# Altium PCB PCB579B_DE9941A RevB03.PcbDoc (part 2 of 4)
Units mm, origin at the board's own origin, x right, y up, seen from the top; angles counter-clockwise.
Board outline 85.8 x 54.18 mm, 6 copper layers (Top, L2C, L3C, L4C, L5C, Bottom), stack 1.627 mm thick; 536 components, 371 nets, 1413 pads, 798 vias.
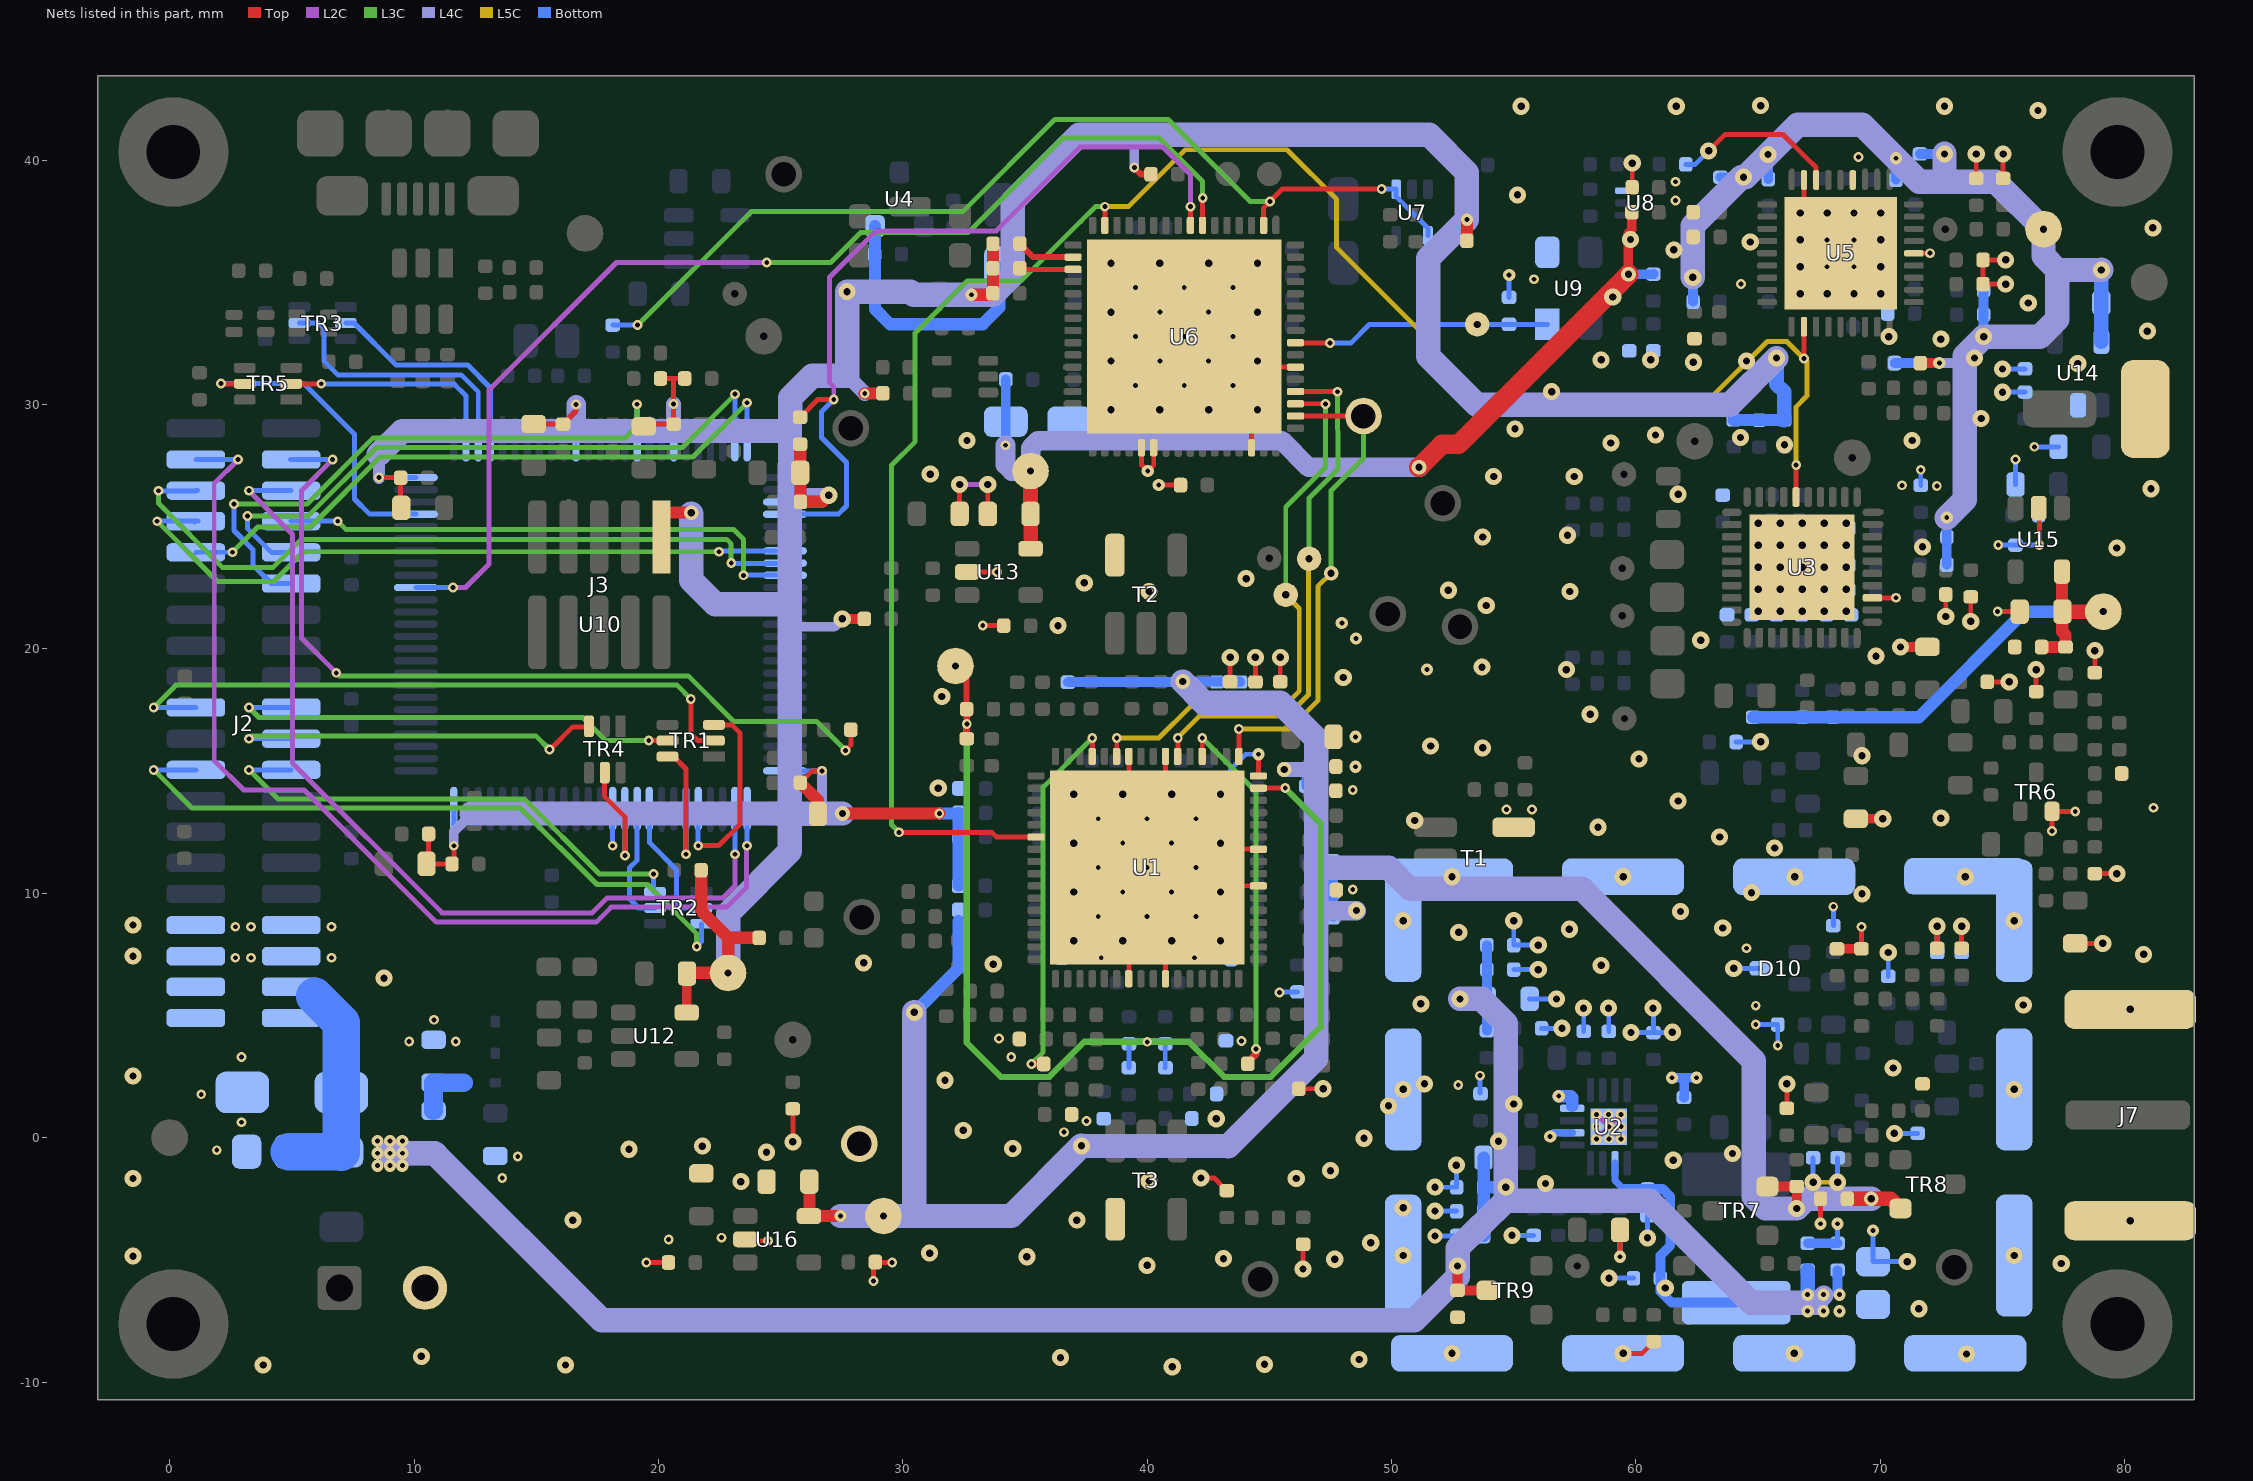
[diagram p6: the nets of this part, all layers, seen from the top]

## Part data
C1 C9 C10: library part CAP_TAJA_10uF_16V, "10uF 16V 10% TAJA Tant Capacitor"
C2 C3 C5 C6 C7 C8 C12 C15 C32 C35 C38 C41 C42 C44 C46 C47 C67 C68 C73 C75 C76 C80 C115 C117 C132 C139 C141 C143 C144 C146 C148 C153 C154 C156 C162 C165 C185: library part CAP0402_10000_X7R_25V_±10%, "0402 Cer. Cap. 10nF 25V X7R ±10%"
C4 C11 C20 C21 C22 C23 C24 C25 C34 C103 C104 C105 C106 C107 C108 C109 C111 C113 C114 C149 C150 C193: library part CAP0402_100000_X7R_16V_±10%, "0402 Cer. Cap. 100nF 16V X7R ±10%"
C13 C51 C52 C62 C69: library part "CAP0402_100p_C0G_25V_± 5%", "0402 Cer. Cap. 100pF±5% 25V C0G"
C14 C16 C17 C36 C50 C54 C59 C61 C70 C102 C110 C118 C126 C134 C135 C151 C152 C160 C163 C170 C186: library part "CAP0402_1000_C0G_25V_± 5%", "0402 Cer. Cap. 1000pF±5% 25V C0G"
C18 C45 C84 C87 C93 C96 C99 C116 C119 C122 C136 C138 C180 C183 C188 C189 C199: library part CAP0402_DNF, "Pads for 0402 Ceramic Capacitor"
C19 C33 C112: library part CAP0402_2200000_X5R_16V_±10%, "0402 Cer. Cap. 2.2uF 16V X5R ±10%"
C26 C27 C28 C29 C30 C31 C78 C81 C82 C86 C88 C89 C92 C94 C97 C194: library part CAP0603_10000000_X5R_10V_±20%, "0603 Cer. Cap. 10uF±20% 10V X5R"
C37 C39 C40 C43 C65 C66 C72 C74 C79 C131 C140 C142 C145 C147 C181: library part CAP0402_33p±5%_C0G_25V, "0402 Cer. Cap. 33pF±5% 25V C0G"
C48 C53 C71: library part "CAP0402_470p_C0G_25V_± 5%", "0402 Cer. Cap. 470pF±5% 25V C0G"
C49: library part CAP0402_47000_X7R_25V_±10%, "0402 Cer. Cap. 47nF 25V X7R ±10%"
C55 C57 C58 C60 C63 C64: library part CAP0402_33000_X7R_25V_±10%, "0402 Cer. Cap. 33nF 25V X7R ±10%"
C56: library part "CAP0402_220p_C0G_25V_± 5%", "0402 Cer. Cap. 220pF±5% 25V C0G"
C77: library part CAP0402_1000000_X5R_10V_±10%, "0402 Cer. Cap. 1uF 10V X5R ±10%"
C83 C85 C91 C95 C98 C155 C184 C196 C197: library part CAP0603_1000000_X7R_16V_±10%, "0603 Cer. Cap. 1uF±10% 16V X7R"
C90: library part CAP0805_DNF, "Unused pads for 0805 Ceramic Capacitor"
C100: library part CAP0402_4700_X7R_25V_±5%, "0402 Cer. Cap. 4.7nF 25V X7R ±5%"
C101: library part "CAP0402_180p_C0G_25V_± 5%", "0402 Cer. Cap. 180pF±5% 25V C0G"
C120 C121: library part CAP0402_10p±5%_C0G_25V, "0402 Cer. Cap. 10pF±5% 25V C0G"
C123 C125 C158 C159 C176 C178 C179 C182 C200: library part CAP0402_5p6±0.1pF_C0G_50V, "0402 Cer. Cap. 5.6pF±0.1pF 50V C0G"
C124: library part CAP0402_3p3±0.1pF_C0G_50V, "0402 Cer. Cap. 3.3pF±0.1pF 50V C0G"
C127 C128: library part CAP0603_2000_C0G_50V_±2%_0805, "0603 Cer. Cap. 2000pF±2% 50V C0G (on 0805 pads)"
C129 C130: library part "CAP0603_1500_C0G_50V_± 5%", "0603 Cer. Cap. 1500pF±5% 50V C0G"
C133 C172: library part CAP0402_1p5±0.1pF_C0G_50V, "0402 Cer. Cap. 1.5pF±0.1pF 50V C0G"
C137 C177 C190 C191: library part CAP0402_6p8±0.1pF_C0G_25V, "0402 Cer. Cap. 6.8pF±0.1pF 25V C0G"
C157 C173 C174 C175: library part "CAP0402_56p_C0G_25V_± 5%", "0402 Cer. Cap. 56pF±5% 25V C0G"
C161: library part CAP0805_10000000_X7R_10V_±10%, "0805 Cer. Cap. 10uF±10% 10V X7R"
C164: library part "CAP0402_330p_C0G_25V_± 5%", "0402 Cer. Cap. 330pF±5% 25V C0G"
C166 C167: library part CAP0402_0p5±0p05_C0G_50V, "0402 Cer. Cap. 0.5pF±0.05pF 50V C0G"
C168 C169: library part CAP0402_47p±5%_C0G_25V, "0402 Cer. Cap. 47pF±5% 25V C0G"
C171: library part CAP0402_2p0±0.1pF_C0G_25V, "0402 Cer. Cap. 2.0pF±0.1pF 25V C0G"
C187: library part CAP0402_4p7±0.1pF_C0G_50V, "0402 Cer. Cap. 4.7pF±0.1pF 50V C0G"
C192 R2 R3 R20 R24 R25 R35 R36 R80 R82 R107 R108 R109 R110 R119 R144 R145: library part R0402_0R, "Resistor 0402 0R 0.063W"
C195 C198: library part CAP0402_8p2±0.1pF_C0G_25V, "0402 Cer. Cap. 8.2pF±0.1pF 25V C0G"
D1: "BAS16HT,  Signal Diode, SOD323"
D2 D3: "HSMF-C165,  Mini Bi-colour Red+Green LED (0603)"
D4: library part LED0603_Green, "Green 0603 LED, KPT-1608CGCK"
D5 D6: "NSR05T40XV2,  Schottky Diode, SOD-523"
D7: library part SMAJ5_0A, "5V Transient Suppression Diode, DO-214AC"
D8: "MMBD1503A, Dual small signal diodes, SOT23"
D9 D10: "BAR64-04W,  Dual Si PIN diode SOT323"
F1: "MF-NSMF150, PTC Resettable Fuse, 1206"
FID1 FID2 FID3: "1.5mm round pad Fiducial"
J2: library part HDR_SMT_20x2_127, "20+20 SMT header, 1.27mm pitch (Archer M50 )"
J3: library part HDR_5X2_127_SMTUnshr, "5x2 header plug  1.27mm, SMT Unshrouded"
J4: library part USB-MICRO-B_ZX62, "R/A USB Micro-B receptacle (Hirose ZX62-B-5PA(33))"
J5: library part MKDS_2w_3_5mm, "2-WAY PCB screw terminal block - MKDS 1/ 2-3,5 HT BK"
J6: library part "RG178 PAD", "Pads for screened wire, e.g. RG 178"
J7: library part SMA_ENDL_J502, "J502 End Launch SMA Socket for 1.6mm PCBs"
L1: library part "Ferrite 0402 10R_BLM15AG100SN1", "0402 ferrite, Z=10R @ 100MHz, BLM15AG100SN1"
L2 L3: library part "Ferrite 0603_600R", "Ferrite, 0603, 600R @ 100MHz 1.3A"
L4 L6 L17 L18 L22: library part IND0603CS_18nH_5%, "Coilcraft 0603CS-18NXJL    Blue"
L5 L8: library part IND0603CS_DNF, "Pads for Coilcraft 0603 Inductor"
L7: library part IND0603CS_68nH_5%, "Coilcraft 0603CS-68NXJL   Orange"
L9 L10 L11: library part IND0603CS_27nH_5%, "Coilcraft 0603CS-27NXJL    Gray"
L12 L13: library part IND0603CS_100nH_5%, "Coilcraft 0603CS-R10XJL 100nH Blue"
L14: library part IND0402CS_5n6_5%, "0402 inductor, 5.6nH, 0402CS-5N6XJL"
L15: library part IND0603, "Coilcraft 0603CS"
L16: library part IND_1515SQ-82NJ, "82nH, Coilcraft Square Air Core inductor 1515SQ-82NJ"
L19: library part IND0603CT_2n2_5%, "Coilcraft 0603CT-2N2XJL"
L20: library part FER0402_0R, "0R 0402 placeholder for ferrite"
L21: library part IND0603CS_4n7_5%, "Coilcraft 0603CS-4N7XJL    Violet"
L23: library part IND0603CS_12nH_5%, "Coilcraft 0603CS-12NXJL    Yellow"
M1 M2 M3 M4: library part 2mmMntngHole, "2mm mounting hole"
MODBO1: library part "SERIAL_small box", "serial number box 10*5mm"
MODBO2: library part 6_LAYER_BOX_SML, "6_LAYER_BOX_SML"
P1 P2 P3 P4 P5 P6 P7 P8 P9 P10 P11 P12 P13 P14 P15 P16 P17 P18 P19 P20 P21 P22 P23 P24 P25 P26 P27 P28 P29 P30 P31 P32 P33 P34 P35 P36 P37 P38 P39 P40 P41 P42 P43 P44 P45 P46 P47 P48 P49 P50 P51 P52 P53 P54 P55 P56 P57 P58 P59 P60 P61 P62 P63 P64 P65 P66 P67 P68 P69 P70 P71 P72 P89 P91: library part TINY_PAD, "Very Small Pad - used to remove all of the 'unconnected pin' errors from ERC & DRC"
R1 R4 R5 R6 R11 R13 R14 R15 R23 R41 R42 R46 R51 R62 R72 R73 R81 R83 R84 R115 R123: library part R0402_100000_100k, "Resistor 0402 100k 1% 0.063W  ( O1D )"
R7 R8 R9 R86 R88 R89 R111 R116 R117 R133 R140 R141 R146 R147: library part R0402_10R, "Resistor 0402 10R 1% 0.063W   ( 01X )"
R10 R29: library part R0402_470R, "Resistor 0402 470R 1% 0.063W  ( 66A = 475R )"
R12 R127 R128 R132 R134: library part R0402_47R, "Resistor 0402 47R 1% 0.063W  ( 66X = 47.5R )"
R16: library part R0402_220R, "Resistor 0402 220R 1% 0.063W (34A = 221R )"
R17 R98 R99 R105 R124 R125 R126: library part R0402_10000_10k, "Resistor 0402 10k 1% 0.063W  ( 01C )"
R18 R90 R91 R92 R93: library part R0402_4R7, "Resistor 0402 4.7R 1% 0.063W  ( 66Y = 4R75 )"
R21 R22 R26 R27 R79: library part R0402_270R, "Resistor 0402 270R 1% 0.063W   ( 42A = 267R )"
R28 R48 R49 R65 R66 R85 R87: library part R0402_1000_1k0, "Resistor 0402 1k0 1% 0.063W  ( 01B )"
R30 R31 R76 R97 R100 R101 R102 R120 R121 R122 R139 R143: library part R0402_DNF, "Pads for Resistor 0402"
R32 R33 R34 R37 R38 R39 R63 R64 R75 R77 R78 R106 R112 R113 R118: library part R0402_3R3, "Resistor 0402 3.3R 1% 0.063W   ( 51Y )"
R40 R43 R57 R71 R74: library part R0402_47000_47k, "Resistor 0402 47k 1% 0.063W  ( 66C = 47.5k )"
R44 R45 R50 R67 R68: library part R0402_4700_4k7, "Resistor 0402 4.7k 1% 0.063W  ( 66B = 4k75 )"
R47: library part R0402_470000_470k, "Resistor 0402 470k 1% 0.063W  ( 66D = 475k )"
R52 R56 R59 R61: library part R0402_100R, "Resistor 0402 100R 1% 0.063W  ( 01A )"
R53 R129: library part R0402_1800_1k8, "Resistor 0402 1.8k 1% 0.063W  ( 26B = 1.82k )"
R54 R60 R136 R137: library part R0402_150R, "Resistor 0402 150R 1% 0.063W  ( 18A )"
R55 R58: library part R0402_24R, "Resistor 0402 24R 1% 0.063W  ( 38X = 24.3R )"
R69 R70: library part R0402_330000_330k, "Resistor 0402 330k 1% 0.063W  ( 51D = 332k )"
R94 R95 R96: library part R0402_18R, "Resistor 0402 18R 1% 0.063W  ( 26X = 18.0R )"
R103 R104: library part R0402_6800_6k8, "Resistor 0402 6.8k 1% 0.063W  ( 81B = 6.81k )"
R114: library part R0402_820R, "Resistor 0402 820R 1% 0.063W  ( 89A )"
R130 R131: library part R0402_12R, "Resistor 0402 12R 1% 0.063W    (09X = 12.1R)"
R135: library part R0402_39R, "Resistor 0402 39R 1% 0.063W  ( 58X = 39.2R )"
R138: library part R0402_180R, "Resistor 0402 180R 1% 0.063W  ( 26A = 182R )"
R142: library part R0402_1000000_1M0, "Resistor 0402 1M0 1% 0.063W   ( 01E )"
SW1: library part MCIPTG_RESETSW, "MCIPTG23K-V 4.3x2.8mm mom. switch - RESET"
T1: library part ETC1-1T-75, "MABA-007748, RF transformer"
T2: "TC1-1-13M+, RF transformer  1:1"
T3: "TC4-14+, RF transformer  4:1"
TL1 TL2 TL3 TL4 TL5 TL6 TL7 TL8 TL9 TL10: library part TESTLOOP_1MM, "Yellow 1.5mm testloop (1.0 mm hole)"
TP1 TP3 TP5 TP6 TP14 TP15 TP16 TP18 TP19 TP23 TP26: library part "1MM TSTPOINTV", "1.0mm Testpoint with via"
TP2 TP4 TP8 TP9 TP10 TP11 TP12 TP13 TP17 TP20: library part "1.5MM TSTPOINTV", "1.5mm Testpoint with via"
TP24 TP25: library part "1MM TESTPOINT", "1mm Testpoint"
TR1 TR2 TR3 TR4 TR5: library part MUN5214DW1T1G, "MUN5214DW dual NPN transistor w/bias resistors, SOT-363"
TR6: "BFR193W, Low noise NPN HF transistor, SOT-323"
TR7 TR8: "BC856A, PNP GP transistor, SOT23"
TR9: "BCW60D  NPN GP transistor"
U1: library part "CMX998 (REV B) L1-L2edge", "CMX998_Q1, Cartesian Feedback Loop based linear transmitter"
U2: "RF5110G, 3V GSM Power Amp, QFN-16"
U3: library part CMX994E_Q4_L1-L2edge, "CMX994EQ4, Direct Conversion Receiver"
U4: "DS1818R-10+, 3.3V EconoReset with Pushbutton 10%, SOT23"
U5: "LMX2571, Low-power RF Synthesizer, Frac-N PLL with FSK modulation, WQFN-36"
U6: library part CMX7364Q1_L1-L2edge, "CMX7364Q1, dPMR Digital Radio Processor"
U7: library part SN74AUP1G80DCK, "74AUP1G80DCK, Single  +edge D-type F-F, SC70-5"
U8: library part SN74AHC1G04DRL, "74AHC1G04DRL, Single Inverter Gate, SOT553"
U9: "MP08120, 38.4MHz, GTXO-91V/X 3.2x2.5mm TCXO clipped sine"
U10: "STM32F103VET6, ARM-based 32-bit MCU 512kb Flash,  LQFP100"
U11: library part USBLC6-2SC6, "USBLC6-2SC6, VLCap ESD Protection, SOT23-6L"
U12 U13 U14 U15 U16: "LP5907MFX-3.3,   3.3V, 250mA ULN Low-IQ LDO Regulator, SOT23-5"
U17: "NC7SZU04P5X, Single Inverter, SC70-5"
U19: "STLQ015M18, 1.8V, 150mA Ultra-low quiescent current regulator, SOT23-5L"
X1: "MP03952, CM8V-T1A Crystal 32.768kHz 9pF +/-20ppm"

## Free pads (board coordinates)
  rrect50% 5x1.5 smd far side paste-2: 1(73.475,-8.825) 2(66.475,-8.825) 3(59.475,-8.825) 4(52.475,-8.825) 8(52.475,10.675) 9(59.475,10.675) 10(66.475,10.675) 11(73.475,10.7)
  rrect50% 1.5x5 smd far side paste-2: 5(50.475,-4.825) 6(50.475,1.975) 7(50.475,8.875) 12(75.475,8.875) 13(75.475,1.975) 14(75.475,-4.825)

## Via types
v1: diameter 0.4, hole 0.2, Top to Bottom, tented both sides, 372 vias
v2: diameter 0.7, hole 0.3, Top to Bottom, tented both sides, 177 vias
v3: diameter 0.7, hole 0.3, L5C to Bottom, tented both sides, 52 vias
v4: diameter 0.5, hole 0.2, Top to Bottom, tented both sides, 35 vias
v5: diameter 0.7, hole 0.3, Top to L2C, tented both sides, 33 vias
v6: diameter 0.6, hole 0.2, Top to Bottom, tented bottom, 30 vias
v7: diameter 0.6, hole 0.3, Top to L2C, tented bottom, 28 vias
v8: diameter 0.6, hole 0.3, Top to L2C, 24 vias
v9: diameter 0.6, hole 0.3, Top to Bottom, tented both sides, 22 vias
v10: diameter 0.6, hole 0.3, Top to Bottom, tented bottom, 9 vias
v11: diameter 0.5, hole 0.2, Top to Bottom, tented top, 6 vias
v12: diameter 0.45, hole 0.2, Top to Bottom, 5 vias
v13: diameter 0.6, hole 0.3, Top to Bottom, 3 vias
v14: diameter 0.406, hole 0.2, Top to Bottom, tented both sides, 2 vias

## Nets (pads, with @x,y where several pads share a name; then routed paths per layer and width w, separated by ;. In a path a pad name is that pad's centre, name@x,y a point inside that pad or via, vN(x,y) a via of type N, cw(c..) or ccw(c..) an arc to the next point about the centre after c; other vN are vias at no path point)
38M4_REF: R12.2 U5.34 | length 7
  Top w0.2: v2(62.975,40.375) 63.65,41.05 66.006,41.05 67.006,40.05 67.368,39.695 U5.34@67.372,39.185 U5.34@67.372,39.135
  Bottom w0.2: R12.2@62.042,39.822 62.422,39.822 v2(62.975,40.375)
998_FBI: TP6.1 U1.38 U6.36 | length 21.6
  Top w0.2: U1.38@41.254,15.509 v1(41.254,16.355) ; U6.36@45.967,30.528 47.778,30.528 v1(47.787,30.52)
  L3C w0.2: TP6.1@46.624,23.689 46.624,26.173 47.812,27.361 v1(47.787,30.52)
  L5C w0.2: v1(41.254,16.355) 42.156,17.258 45.744,17.258 46.602,18.115 TP6.1@46.602,23.665
998_FBQ: TP5.1 U1.43 U6.35 | length 23.2
  Top w0.2: U1.43@38.754,15.509 v1(38.754,16.355) ; U6.35@45.967,30.028 v1@47.298,30.028
  L2C w0.2: TP5.1@45.634,22.216 TP5.1@45.647,22.23
  L3C w0.2: TP5.1@45.669,22.208 45.669,25.803 47.309,27.443 47.292,27.459 v1(47.292,30.018)
  L5C w0.2: v1(38.754,16.355) 40.484,16.355 41.764,17.635 45.588,17.635 46.224,18.272 46.224,21.653 TP5.1@45.669,22.208 TP5.1@45.669,22.241
+3V3_VCO: C92.1 R86.1 R88.2 R89.1 R90.1 R91.1 R92.1 R93.1 R98.1 R99.2 R117.2 R118.2 TP10.1 U14.5 | length 53.4
  Top w0.4: R99.2@71.64,31.69 71.643,31.694 v4(72.413,31.694)
  L4C w0.4: v4(72.413,31.694) 73.445,31.694 73.45,31.6
  L4C w1: v2(62.325,35.2) 62.325,37.316 64.309,39.3 v2(64.4,39.3) 64.475,39.3 v2(65.4,40.225) 66.625,41.45 69.261,41.45 v4(70.635,40.076) 71.59,39.121 72.529,39.121 ; v2(72.625,40.25) 72.625,39.218 72.529,39.121 ; v4(72.718,25.37) 73.448,26.1 73.45,31.6 ; 73.445,31.694 73.445,31.995 v2(74.225,32.775) 76.525,32.775 77.239,33.489 77.239,35.5 ; v2(79.042,35.504) 77.239,35.5 ; 72.529,39.121 74.729,39.121 TP10.1@76.675,37.175 76.675,36.075 77.239,35.5
  Bottom w0.4: R91.1@62.335,34.205 v2@62.335,35.19 ; R90.1@63.457,39.297 v2@64.397,39.297 ; v2(65.4,40.225) R89.1@65.414,39.222 ; R88.2@70.596,31.69 70.6,31.694 v4(72.413,31.694) ; R86.1@70.635,39.202 v4(70.635,40.076) ; R93.1@71.625,40.25 v2(72.625,40.25) ; R118.2@72.718,23.447 v4(72.718,25.37) ; v2(74.225,32.775) R98.1@74.225,33.675 R92.1@74.225,34.675
  Bottom w0.6: U14.5@79.042,32.567 C92.1@79.042,34.158 v2(79.042,35.504)
+3V3A: C9.1 C86.1 R2.1 R8.2 R9.2 TP9.1 U13.5 | length 40.7
  Top w0.4: U13.5@35.231,24.098 35.231,24.427 ; v9@59.688,35.336 59.688,36.993 59.832,37.138 R8.2@59.832,37.866
  Top w0.6: C86.1@35.227,25.522 TP9.1@35.227,27.275 ; 35.231,24.427 C86.1@35.231,25.519
  Top w0.8: v13(51.123,27.427) 52.063,28.367 52.738,28.367 v9@59.688,35.316 ; v9@59.688,35.336 v9@59.688,35.316 ; v9(59.698,35.326) v9@59.688,35.316
  L4C w0.8: v1(34.204,28.33) 34.204,27.536 34.465,27.275 TP9.1@35.227,27.275 35.227,28.214 35.532,28.519 45.514,28.519 46.607,27.427 v13(51.123,27.427)
  Bottom w0.4: v1@34.214,28.33 C9.1@34.214,29.297 R2.1@34.214,31.022 ; v9(59.698,35.326) R9.2@60.714,35.334
+3V3A_RX: C94.1 C115.2 R101.2 R106.2 R112.2 R113.2 TP12.1 U15.5 | length 21.9
  Top w0.508: C115.2@76.6,20.075 R101.2@77.575,20.075 77.575,20.575 77.45,20.7 C94.1@77.45,21.525 ; C94.1@77.433,21.52 U15.5@77.433,23.162
  Top w0.6: C94.1@77.45,21.525 TP12.1@79.125,21.525
  Bottom w0.508: R113.2@64.793,17.208 R106.2@66.8,17.208 R112.2@68.044,17.208 70.925,17.2 71.575,17.2 75.9,21.525 TP12.1@79.125,21.525
+3V3A_TX: C97.1 C149.2 R32.2 R33.2 R34.2 R37.2 R63.2 R64.2 R75.2 R77.2 R78.2 R123.2 TP13.1 TR7.2 TR8.2 U16.5 | length 110.2
  Top w0.4: TR7.2@65.375,-2 R123.2@66.575,-2 v2(66.575,-2.9) ; C149.2@68.65,-2.5 C149.2@68.85,-2.5
  Top w0.5: U16.5@26.161,-3.21 27.45,-3.21 v4(27.455,-3.205) ; U16.5@26.177,-3.194 C97.1@26.185,-1.802
  Top w0.6: C149.2@68.85,-2.5 v13(69.625,-2.5) 70.425,-2.5 TR8.2@70.825,-2.9
  L4C w0.6: v9(45.605,15.06) 46.585,15.06 46.925,15.4 ; v2@48.562,9.275 v2(48.562,9.291)
  L4C w0.8: 46.925,9.275 v2@48.562,9.275
  L4C w1: v4(27.455,-3.205) TP13.1@29.208,-3.205 30.475,-3.205 ; v2(30.475,5.125) 30.475,-3.205 ; v9(41.45,18.664) 42.314,17.8 45.45,17.8 46.925,16.325 46.925,15.4 46.925,11.05 ; v13(69.625,-2.5) 66.975,-2.5 v2(66.575,-2.9) 65.3,-2.9 64.825,-2.425 64.825,3.15 57.8,10.175 50.755,10.175 49.88,11.05 46.925,11.05 ; 30.475,-3.205 34.44,-3.205 v2(37.31,-0.335) 43.325,-0.35 46.925,3.25 46.925,9.275 46.925,11.05
  Bottom w0.381: R77.2@47.63,9.291 v2(48.562,9.291)
  Bottom w0.4: R63.2@36.765,18.632 36.776,18.643 v9@41.45,18.643 ; v2@37.328,-0.318 R78.2@39.241,-0.318 ; v9(41.45,18.664) 43.784,18.664 R75.2@43.805,18.643 ; v9(45.605,15.06) 46.28,15.06 46.505,14.835 R37.2@46.505,14.385 ; R77.2@47.604,9.037 R33.2@47.604,10.016 R34.2@47.604,11.312
  Bottom w0.5: v2(30.475,5.125) 32.281,6.931 32.281,8.85
+3V3D: C10.1 C20.2 C21.2 C22.2 C23.2 C24.2 C26.2 C27.2 C28.2 C29.2 C30.2 C81.1 C193.2 C194.2 D1.1 J3.1 R1.1 R3.1 R4.2 R5.2 R6.2 R7.1 R13.2 R15.1 R17.1 R18.1 R23.2 R38.2 R39.2 R46.2 R79.1 R111.2 R115.2 R116.1 R133.1 R145.1 TP8.1 U4.2 U10.11 U10.19 U10.28 U10.50 U10.75 U10.100 U12.5 | length 205.6
  Top w0.203: v1(8.566,27.008) C193.2@9.443,27.008 ; C194.2@9.454,25.797 C193.2@9.454,26.997 ; C26.2@10.599,11.293 C20.2@10.599,12.426 ; C26.2@10.667,11.198 R15.1@11.554,11.198 ; R15.1@11.629,11.274 v1(11.629,11.945) ; C29.2@14.896,29.198 C24.2@16.096,29.198 16.632,29.734 v1(16.632,29.995) ; C28.2@19.429,29.197 C23.2@20.629,29.197 20.619,29.207 v1(20.619,30.021) 20.619,31.037 ; R17.1@20.086,31.062 R18.1@21.077,31.062 ; J3.1@20.124,24.578 J3.1@20.125,25.575 ; C21.2@25.804,14.522 26.29,15.008 v1(26.693,15.008)
  Top w0.254: v1(39.475,39.691) 39.743,39.423 R4.2@40.155,39.423
  Top w0.381: U12.5@21.157,5.114 C81.1@21.157,6.698 ; C81.1@21.174,6.714 C81.1@21.199,6.714
  Top w0.4: v2(27.525,21.225) R145.1@28.425,21.225
  Top w0.5: J3.1@20.125,25.575 v9(21.35,25.575) ; v4(32.814,34.488) R3.1@33.63,34.488 ; R3.1@33.689,34.547 R5.2@33.689,35.572 ; R5.2@33.692,35.575 R6.2@33.692,36.578 ; R7.1@53.084,36.698 v4(53.084,37.562)
  Top w0.508: C81.1@21.199,6.74 TP8.1@22.85,6.74 22.85,8.181 ; R23.2@21.747,10.944 21.747,9.284 22.85,8.181 ; R79.1@24.112,8.181 22.85,8.181 ; C21.2@25.804,14.522 26.532,13.794 C30.2@26.532,13.252 ; R13.2@25.803,28.372 C27.2@25.803,27.208 25.815,27.208 C22.2@25.815,26.167 ; C22.2@25.815,26.013 26.701,26.013 v2(26.972,26.284) ; v9(27.533,13.264) v1(31.495,13.264) ; v1(28.446,30.45) 29.178,30.45 R133.1@29.184,30.455
  L4C w0.4: v1(11.629,11.945) 11.629,12.531 12.362,13.264 ; 16.6,28.914 16.632,28.946 ; 25.375,20.9 27.2,20.9 v2(27.525,21.225) ; v1(26.693,15.008) 26.7,13.25 ; v1(39.475,39.691) 39.475,40.813
  L4C w0.508: v1(8.566,27.008) 8.566,27.959
  L4C w0.6: 20.619,28.914 v1(20.619,30.021) ; 25.375,26.3 v2(26.972,26.284) ; 27.719,31.176 v1(28.446,30.45)
  L4C w0.8: 16.632,28.946 v1(16.632,29.995)
  L4C w1: 8.566,27.959 9.521,28.914 16.6,28.914 20.619,28.914 25.385,28.914 ; 12.362,13.264 25.375,13.25 ; v9@21.35,25.525 21.35,22.8 22.325,21.825 25.375,21.825 ; TP8.1@22.85,6.74 22.85,9.184 25.382,11.716 25.375,13.25 ; v9(27.533,13.264) 26.7,13.25 25.375,13.25 ; v2(65.75,31.9) 63.835,29.985 53.49,29.985 51.5,31.975 51.5,35.978 v4(53.084,37.562) 53.084,39.492 51.534,41.041 37.219,41.041 34.501,38.324 34.501,35.301 33.688,34.488 v4(32.814,34.488) 30.442,34.488 30.315,34.615 v2(27.719,34.615) 27.719,31.176 26.296,31.176 25.395,30.275 25.385,28.914 ; 25.375,13.25 25.375,20.9 25.375,21.825 ; 25.375,21.825 25.375,26.3 25.385,28.914
  Bottom w0.203: v1(8.566,27.008) U10.100@10.079,27.008 ; v1(11.629,11.945) U10.75@11.629,13.458 ; U10.11@16.629,28.473 U10.11@16.636,28.481 ; U10.11@16.629,28.558 16.632,28.561 v1(16.632,29.995) ; U10.19@20.629,28.558 v1@20.629,30.021 ; U10.50@25.179,15.008 v1(26.693,15.008)
  Bottom w0.254: U10.28@25.179,26.008 26.697,26.008 v2(26.972,26.284)
  Bottom w0.5: R46.2@32.291,10.314 R38.2@32.291,12.314 R39.2@32.291,13.289 ; R111.2@64.006,29.365 R116.1@65.039,29.365 ; R116.1@65.047,29.365 R115.2@66.063,29.365
  Bottom w0.508: v2@27.733,34.629 D1.1@28.864,34.629 ; U4.2@28.864,37.297 D1.1@28.864,34.629 ; v1@31.521,13.264 R39.2@32.265,13.264 ; C10.1@33.948,35.566 33.948,33.967 33.264,33.283 29.479,33.283 28.864,33.898 D1.1@28.864,34.629
  Bottom w0.6: v2(65.75,31.9) 65.75,30.828 66.063,30.515 R115.2@66.063,29.365
+V: C90.2 C150.2 C161.2 C162.2 C163.2 C164.2 C165.2 C168.2 C169.2 C170.2 C184.2 C185.2 C186.2 D7.1 F1.2 J2.37 J2.38 J2.39 J2.40 L3.1 L15.1 L16.1 L20.1 TR9.3 U2.14 | length 109.4
  Top w0.4: v2(52.7,-5.25) C150.2@52.7,-6.25 TR9.3@53.925,-6.25
  L4C w0.8: 67.375,-6.75 v11@67.675,-6.45
  L4C w1: v4(9.015,-0.64) v4(9.525,-0.64) 10.84,-0.64 17.675,-7.475 50.925,-7.475 52.7,-5.7 v2(52.7,-5.25) 52.7,-4.525 54.675,-2.575 ; v2(52.8,5.675) 53.675,5.675 54.675,4.675 v2(54.675,-2.025) 54.675,-2.575 ; 67.375,-6.75 64.725,-6.75 60.55,-2.575 54.675,-2.575
  Bottom w0.3: U2.14@59.139,-1.053 59.139,-1.753 59.489,-2.103
  Bottom w0.4: L20.1@53.9,4.375 C184.2@53.9,5.675 C185.2@53.9,6.875 C186.2@53.9,7.875 ; 59.489,-2.103 C168.2@60.475,-2.1 61.1,-2.1 61.4,-2.4 61.4,-4.425 61,-4.825 C170.2@61,-5.75 61,-6.3 61.45,-6.75 L16.1@64.1,-6.75 ; C169.2@68.25,-5.425 68.25,-6.35 v11(68.325,-6.425)
  Bottom w0.508: C162.2@53.764,-4.025 C163.2@53.764,-3.009 C164.2@53.764,-2.028 ; L15.1@53.764,-0.828 C164.2@53.764,-2.028 ; v2(54.675,-2.025) C164.2@53.764,-2.028
  Bottom w0.6: v2(52.8,5.675) C184.2@53.9,5.675 ; v11(67.025,-6.425) C165.2@67.025,-5.425
  Bottom w1: v4(9.525,-0.64) 9.535,-0.65 L3.1@10.8,-0.65
  Bottom w1.524: C90.2@4.9,-0.575 F1.2@7,-0.575 ; 5.941,5.786 7.025,4.702 D7.1@7.025,1.85 F1.2@7.025,-0.6
  other v4: 8.507,-1.148 9.015,-1.148 9.523,-1.148 8.507,-0.64 8.507,-0.132 9.015,-0.132 9.523,-0.132
  other v11: 67.025,-7.1 67.675,-7.1 68.325,-7.1 67.675,-6.425
+VFILT: C88.1 D6.2 L3.2 | length 2.4
  Bottom w0.762: L3.2@10.8,1.1 C88.1@10.8,2.25 D6.2@12.025,2.25
ALARM: U10.62 | length 1.5
  Bottom w0.203: v1(18.129,11.945) U10.62@18.129,13.458
AUX_IN_1: J2.19 TR1.5 | length 19.4
  Top w0.203: v1(19.606,16.253) 20.363,16.253 TR1.5@20.373,16.243
  L3C w0.203: v1(3.249,17.597) 3.655,17.191 16.908,17.191 17.846,16.253 v1(19.606,16.253)
  Bottom w0.203: v1(3.249,17.597) J2.19@4.976,17.597
AUX_IN_1B: TR1.3 U10.55 | length 8.5
  Top w0.203: v1(21.629,11.945) 22.461,11.945 23.344,12.829 23.344,16.553 23.005,16.893 TR1.3@22.273,16.893
  Bottom w0.203: v1(21.629,11.945) U10.55@21.629,13.458
AUX_IN_2: J2.20 TR1.2 | length 26.8
  Top w0.203: v1@21.333,17.951 21.333,16.532 21.623,16.243 TR1.2@22.273,16.243
  L3C w0.203: v1(-0.651,17.597) 0.263,18.512 20.767,18.512 v1(21.328,17.951)
  Bottom w0.203: v1(-0.651,17.597) J2.20@1.076,17.597
AUX_IN_2B: TR1.6 U10.56 | length 6.3
  Top w0.203: TR1.6@20.373,15.593 20.622,15.593 21.129,15.085 v1(21.129,11.595)
  Bottom w0.203: v1(21.129,11.595) U10.56@21.129,13.458
AUX_OUT_1: TR2.2 U10.59 | length 5.3
  Bottom w0.203: U10.59@19.629,13.458 19.629,12.08 20.743,10.966 20.743,9.63 20.972,9.402 TR2.2@21.683,9.402
AUX_OUT_1B: J2.23 TR2.6 | length 20.8
  L3C w0.203: v1(3.249,15.047) 4.433,13.863 14.518,13.863 17.593,10.788 v1(19.804,10.788)
  Bottom w0.203: v1(3.249,15.047) J2.23@4.976,15.047 ; TR2.6@19.804,10.072 v1(19.804,10.788)
AUX_OUT_2: TR2.5 U10.60 | length 5
  Bottom w0.203: U10.60@19.129,13.458 19.129,11.349 18.819,11.038 18.819,9.774 19.191,9.402 TR2.5@19.859,9.402
AUX_OUT_2B: J2.24 TR2.3 | length 28.3
  L3C w0.203: v1(-0.651,15.047) 0.914,13.482 14.36,13.482 17.486,10.356 19.557,10.356 21.568,8.346 v1(21.568,7.824)
  Bottom w0.203: v1(-0.651,15.047) J2.24@1.076,15.047 ; v1(21.568,7.824) 21.759,8.016 TR2.3@21.759,8.752
AUX_OUT_3: TR4.5 U10.61 | length 5.7
  Top w0.203: TR4.5@17.788,15.013 17.788,13.967 18.629,13.125 v1(18.629,11.545)
  Bottom w0.203: v1(18.629,11.545) U10.61@18.629,13.408
AUX_OUT_3B: J2.21 TR4.3 | length 16.3
  Top w0.203: v1(15.544,15.88) 15.569,15.88 16.497,16.808 TR4.3@17.132,16.808
  L3C w0.203: v1(3.249,16.322) 3.355,16.429 14.995,16.429 v1(15.544,15.88)
  Bottom w0.203: v1(3.249,16.322) J2.21@4.976,16.322
AUXDAC2: C18.1 TP1.1 U6.40 U9.1 | length 10.7
  Top w0.203: U6.40@45.967,32.528 45.977,32.518 v1(47.486,32.518)
  Bottom w0.203: v1(47.486,32.518) 48.343,32.518 49.1,33.275 TP1.1@53.5,33.275 54.795,33.269 C18.1@54.807,33.28 U9.1@56.376,33.28
BB_CLK: R16.1 U6.50 U7.1 U7.4 | length 40.8
  Top w0.2: U6.50@44.767,37.228 44.767,38.05 45.535,38.818 v1(49.594,38.818)
  L3C w0.2: v1(19.15,33.25) 23.792,37.892 32.456,37.892 36.228,41.664 40.853,41.664 44.208,38.31 v1(45.022,38.31)
  Bottom w0.2: R16.1@18.13,33.247 v1(19.15,33.25) ; v1(49.594,38.818) U7.1@50.174,38.818 ; U7.1@50.189,38.802 50.189,38.502 51.489,37.202 U7.4@51.489,36.902
BOOTEN1: R6.1 U6.2 | length 2.5
  Top w0.254: R6.1@34.792,36.578 35.342,36.028 U6.2@37.067,36.028
BOOTEN2: R5.1 U6.3 | length 2.2
  Top w0.2: R5.1@34.834,35.528 U6.3@37.067,35.528
BVREF: R50.2 R52.1 R56.2 R57.2 R59.1 R61.2 TP4.1 U1.31 | length 48.5
  Top w0.2: U1.31@44.452,14.307 45.648,14.307 v1(45.65,14.305)
  Top w0.254: TP4.1@32.154,19.299 32.612,18.841 R57.2@32.612,17.535 ; R50.2@32.62,16.323 v1(32.62,16.925) R57.2@32.62,17.552
  L3C w0.254: v1(32.62,16.925) 32.62,3.882 34.017,2.484 35.989,2.484 37.426,3.92 v1(40.003,3.92) 41.709,3.92 43.145,2.484 45.057,2.484 47.107,4.534 47.107,12.848 v1(45.65,14.305) v1@45.646,14.309
  Bottom w0.2: R56.2@39.249,2.861 R52.1@39.249,3.832 ; R61.2@40.734,2.861 40.741,2.868 R59.1@40.741,3.84
  Bottom w0.254: R52.1@39.139,3.92 v1(40.003,3.92) R59.1@40.79,3.92
CDATA: U6.55 U10.91 | length 46.5
  Top w0.203: U6.55@42.272,37.392 v1(42.272,38.442)
  L2C w0.203: v1(11.593,22.508) 12.108,22.508 13.075,23.475 13.075,30.6 18.284,35.809 v1(24.432,35.809)
  L3C w0.203: v1(24.432,35.809) 27.049,35.809 28.268,37.028 32.667,37.028 36.543,40.904 40.49,40.904 42.272,39.122 v1(42.272,38.442)
  Bottom w0.203: U10.91@10.079,22.508 v1(11.593,22.508)
CH1_GREEN: TR3.2 U10.4 | length 9.1
  Bottom w0.203: TR3.2@7.211,33.33 7.544,33.33 9.257,31.618 12.187,31.618 13.129,30.675 U10.4@13.129,28.558
CH1_RED: TR3.5 U10.3 | length 11.2
  Bottom w0.203: TR3.5@5.311,33.33 6.083,33.33 6.322,33.091 6.322,31.77 6.881,31.212 11.933,31.212 12.629,30.515 U10.3@12.629,28.558
CH2_GREEN: TR5.2 U10.2 | length 9.2
  Top w0.203: TR5.2@4.976,30.846 v1(6.206,30.846)
  Bottom w0.203: v1(6.206,30.846) 6.221,30.831 11.653,30.831 12.129,30.354 U10.2@12.129,28.558
CH2_RED: TR5.5 U10.97 | length 12.7
  Top w0.203: v1(2.106,30.856) 2.116,30.846 TR5.5@3.076,30.846
  Bottom w0.203: v1(2.106,30.856) 5.484,30.856 7.564,28.776 7.564,26.135 8.19,25.508 U10.97@10.079,25.508
CLK: U1.54 U3.26 U5.11 U6.63 | length 81.4
  Top w0.2: v1(29.848,12.492) 33.646,12.492 33.83,12.307 U1.54@35.452,12.307 ; U6.63@38.267,37.228 v1(38.267,38.092) ; U5.11@66.872,33.185 v1(66.875,31.875)
  Top w0.203: U3.26@66.556,26.421 v1(66.556,27.521)
  L3C w0.2: v1(29.848,12.492) 29.538,12.802 29.538,27.516 30.503,28.481 30.503,32.923 32.642,35.063 34.853,35.063 37.282,37.491 37.286,37.491 37.887,38.092 v1(38.267,38.092)
  L5C w0.2: v1(38.267,38.092) 39.233,38.092 41.564,40.424 45.722,40.424 47.75,38.396 47.75,36.419 51.828,32.34 51.828,31.197 52.881,30.144 62.944,30.144 65.375,32.575 66.175,32.575 v1(66.875,31.875) 67,31.75 67,30.35 66.556,29.906 v1(66.556,27.521)
CSN: R13.1 U6.56 U10.29 | length 33.8
  Top w0.203: R13.1@25.8,29.475 26.525,30.2 v1(27.175,30.2) ; U6.56@41.772,37.392 v1(41.772,38.092)
  L2C w0.203: v1(27.175,30.2) 27.175,30.725 26.998,30.902 26.998,35.193 28.91,37.104 33.826,37.104 37.247,40.526 40.65,40.526 41.772,39.403 v1(41.772,38.092)
  Bottom w0.203: U10.29@25.179,25.508 27.365,25.508 27.7,25.843 27.7,27.625 26.675,28.65 26.675,29.7 v1(27.175,30.2)
DCMEAS: TL8.1 U1.33 U6.34 | length 20.1
  Top w0.2: U6.34@45.967,29.528 48.847,29.528 TL8.1@48.85,29.525
  Top w0.203: v1(43.75,16.725) U1.33@43.754,15.605
  L3C w0.2: v9(47.525,23.1) 47.525,26.478 47.875,26.828 48.85,27.806 TL8.1@48.85,29.525
  L5C w0.203: v1(43.75,16.725) 45.825,16.725 46.981,17.881 46.981,22.556 v9(47.525,23.1)
ETH_CRS_DV: J2.8 U10.32 | length 29
  L3C w0.203: v1(-0.508,25.223) 1.961,22.754 4.26,22.754 5.479,23.973 5.505,23.947 5.53,23.973 v1(22.479,23.973)
  Bottom w0.203: v1(-0.508,25.223) 0.997,25.223 1.023,25.198 1.062,25.237 J2.8@1.076,25.222 J2.8@1.155,25.222 ; v1@22.453,24.008 25.128,24.008 25.154,23.983 U10.32@25.179,24.008
ETH_MDC: J2.11 U10.16 | length 24.9
  L3C w0.203: v1(2.634,25.922) 5.62,25.922 8.316,28.619 18.633,28.619 19.121,29.106 v1(19.121,30.01)
  Bottom w0.203: v1(2.634,25.922) 2.634,24.842 3.414,24.061 3.414,23.426 4.168,22.672 J2.11@4.976,22.672 ; U10.16@19.121,28.497 v1(19.121,30.01)
ETH_MDIO: J2.10 U10.25 | length 26.6
  L3C w0.203: v1@2.569,23.953 3.605,24.989 5.764,24.989 8.632,27.857 21.415,27.857 v1(23.629,30.072)
  Bottom w0.203: J2.10@1.076,23.947 1.07,23.953 v1(2.572,23.953) ; U10.25@23.629,28.558 v1(23.629,30.072)
ETH_REF_CLK: J2.9 U10.24 | length 26.6
  L3C w0.203: v1(3.193,25.44) 5.676,25.44 8.474,28.238 20.974,28.238 23.129,30.394 v1(23.129,30.422)
  Bottom w0.203: v1(3.193,25.44) 3.193,24.918 4.163,23.947 J2.9@4.976,23.947 ; U10.24@23.129,28.558 v1(23.129,30.422)
ETH_RXD0: J2.6 U10.33 | length 30.1
  L3C w0.203: v1(-0.457,26.468) -0.457,25.953 2.158,23.338 4.241,23.338 5.384,24.481 22.794,24.481 22.979,24.296 v1(22.979,23.508)
  Bottom w0.203: v1(-0.457,26.468) 1.053,26.468 1.067,26.481 J2.6@1.076,26.472 J2.6@1.135,26.472 ; v1@23.037,23.5 25.171,23.5 U10.33@25.179,23.508
ETH_RXD1: J2.7 U10.34 | length 22
  L3C w0.203: v1(6.878,25.22) 7.211,24.887 23.074,24.887 23.479,24.482 v1(23.479,23.008)
  Bottom w0.203: J2.7@4.976,25.222 v1@6.878,25.222 ; v1@23.479,23.021 25.167,23.021 U10.34@25.179,23.008
ETH_TX_EN: J2.3 R139.1 | length 34.7
  Top w0.203: v1(27.658,15.845) 27.872,16.059 R139.1@27.872,16.667 ; R139.1@27.872,16.691 R139.1@27.872,16.667 ; R139.1@27.881,16.699 27.878,16.689 R139.1@27.872,16.667
  L2C w0.203: v1(6.672,27.751) 5.402,26.481 5.402,20.436 v1(6.819,19.02)
  L3C w0.203: v1(6.819,19.02) 6.946,18.893 21.219,18.893 23.082,17.029 26.474,17.029 v1(27.658,15.845)
  Bottom w0.203: J2.3@4.945,27.751 v1(6.672,27.751)
ETH_TXD0: J2.4 U10.51 | length 42.8
  L2C w0.203: v1(2.803,27.747) 1.826,26.77 1.826,15.427 3.025,14.228 5.497,14.228 10.91,8.815 17.451,8.815 18.064,9.428 22.798,9.428 23.609,10.24 23.609,11.925 v1(23.629,11.945)
  Bottom w0.203: J2.4@1.076,27.747 v1(2.803,27.747) ; v1(23.629,11.945) U10.51@23.629,13.458
ETH_TXD1: J2.5 U10.52 | length 37.9
  L2C w0.203: v1(3.249,26.472) 5.021,24.7 5.021,15.329 11.154,9.196 17.293,9.196 17.906,9.809 22.64,9.809 23.129,10.299 v1(23.129,11.595)
  Bottom w0.203: v1(3.249,26.472) J2.5@4.976,26.472 ; v1(23.129,11.595) U10.52@23.129,13.458
FB_I: R65.1 U1.36 | length 15.2
  Top w0.2: U1.36@42.254,15.509 v1(42.254,16.355)
  Top w0.305: v1(44.448,3.627) 44.448,3.405 44.092,3.05 R65.1@44.117,3.024 ; R65.1@44.116,3.023 R65.1@44.117,3.024
  L3C w0.203: v1(42.254,16.355) 44.448,14.161 v1(44.448,3.627)
FB_Q: R49.1 U1.45 | length 15.7
  Top w0.203: U1.45@37.754,15.509 v1(37.754,16.355)
  Top w0.305: v1(35.264,3.014) R49.1@35.769,3.014
  L3C w0.203: v1(35.264,3.014) 35.741,3.492 35.741,14.343 v1(37.754,16.355)
GND: C7.2 C8.2 C9.2 C11.1 C14.1 C15.1 C16.2 C18.2 C37.1 C38.1 C39.1 C40.1 C41.1 C42.1 C43.1 C44.1 C45.2 C48.1 C49.1 C51.1 C57.2 C58.2 C63.2 C64.2 C65.1 C66.1 C67.1 C68.1 C69.1 C71.1 C72.1 C73.1 C74.1 C75.1 C76.1 C77.1 C78.1 C79.1 C80.1 C85.2 C86.2 C87.2 C88.2 C89.2 C90.1 C91.2 C92.2 C93.2 C94.2 C95.2 C96.2 C97.2 C98.2 C99.2 C101.2 C102.2 C103.2 C104.2 C105.2 C106.2 C107.2 C108.2 C109.2 C111.2 C112.2 C113.2 C114.2 C115.1 C116.1 C117.1 C122.1 C123.1 C131.1 C132.1 C137.1 C140.1 C141.1 C142.1 C143.1 C145.1 C146.1 C147.1 C148.1 C149.1 C150.1 C151.1 C152.1 C153.1 C154.1 C155.1 C156.1 C158.1 C159.1 C161.1 C162.1 C163.1 C164.1 C165.1 C168.1 C169.1 C170.1 C176.1 C177.1 C178.1 C179.1 C180.1 C181.1 C182.1 C183.1 C184.1 C185.1 C186.1 C187.1 C188.1 C189.1 C190.2 C191.2 C200.1 D7.2 D10.3 J2.33 J2.34 J2.35 J2.36 J5.2 J6.2 J7.2 J7.3 L7.2 L9.1 L10.2 pad.1 pad.2 pad.3 pad.4 pad.5 pad.6 pad.7 pad.8 pad.9 pad.10 pad.11 pad.12 pad.13 pad.14 R47.1 R55.1 R58.1 R76.1 R81.2 R82.1 R83.2 R84.2 R85.2 R100.2 R105.2 R120.1 R121.1 R132.1 R134.1 R136.1 R137.1 R138.1 T1.4 T2.4 T3.6 TL1.1 TR6.2 U1.7 U1.10 U1.23 U1.26 U1.32 U1.39 U1.42 U1.65 U2.2 U2.4 U2.17 U3.13 U3.41 U5.23 U5.31 U5.35 U5.37 U6.21 U6.22 U6.30 U6.38 U6.65 U8.3 U9.2 U13.2 U14.2 U15.2 U16.2 | length 124.9
  Top w0.2: v1(19.507,-5.108) R84.2@20.413,-5.108 ; U16.2@23.62,-4.219 v1(24.485,-4.219) ; v2(25.5,-0.175) R82.1@25.5,1.175 ; v1(28.803,-5.87) C99.2@28.803,-5.165 ; C99.2@28.896,-5.108 v1(29.565,-5.108) ; C85.2@32.325,25.525 v2(32.325,26.725) ; U13.2@32.633,23.15 v1(33.85,23.15) ; v1(33.272,20.95) C87.2@34.127,20.95 ; v2(33.475,26.725) 33.477,26.723 C86.2@33.477,25.522 ; U1.7@39.252,6.507 U1.65@39.252,10.307 ; U1.65@39.252,11.807 U1.42@39.252,15.607 ; U6.21@39.767,28.228 39.767,27.533 v4(40.025,27.275) 40.267,27.517 U6.22@40.267,28.228 ; v4@40.477,26.702 C11.1@41.365,26.702 ; U1.10@40.752,6.507 U1.65@40.752,8.057 ; U1.65@40.752,10.307 U1.23@44.552,10.307 ; U1.65@40.752,11.807 U1.39@40.752,15.607 ; v2(42.2,-1.65) 42.744,-1.65 R136.1@43.262,-2.167 ; U6.65@42.767,31.528 U6.38@46.067,31.528 ; U1.65@43.002,11.807 U1.26@44.552,11.807 ; C73.1@43.389,18.655 v5@43.389,19.639 ; U6.30@44.267,28.228 U6.65@44.267,30.028 ; R76.1@44.43,18.643 v5@44.43,19.645 ; U1.32@44.555,14.81 v4(44.555,15.685) ; C72.1@45.447,18.652 v5@45.447,19.647 ; R58.1@46.2,2.002 v2(47.2,2) ; v2(46.375,-5.375) 46.38,-5.37 R137.1@46.38,-4.364 ; v4(59.35,-4.875) C155.1@59.35,-3.775 ; v2(59.475,-8.825) 60.25,-8.825 C154.1@60.725,-8.35 ; C14.1@59.84,38.882 59.85,38.892 v5(59.85,39.875) ; C152.1@66.175,1.2 v2(66.175,2.2) ; U5.35@66.872,39.185 66.872,37.685 v6(67.822,36.735) U5.37@68.372,36.185 ; v4(67.55,-3.525) C149.1@67.55,-2.5 ; C158.1@69.225,7.725 v1(69.225,8.625) ; U3.13@69.675,22.075 v1@70.617,22.075 ; U5.23@71.372,36.185 72.027,36.185 v1(72.032,36.19) ; R134.1@72.325,7.75 v2(72.325,8.65) ; v2(72.675,21.325) R120.1@72.675,22.225 ; C159.1@73.325,7.75 v2(73.325,8.65) ; v2(73.7,21.125) R121.1@73.7,22.125 ; C101.2@73.925,39.25 v2(73.925,40.25) ; C122.1@74.375,18.65 v2(75.275,18.65) ; v1(74.8,21.525) C94.2@75.7,21.525 ; R85.2@75.025,39.25 v2(75.025,40.25) ; v2(75.125,34.925) C112.2@74.2,34.923 C111.2@74.2,35.914 v2(75.125,35.915) ; C200.1@76.375,18.25 v2(76.375,19.15) ; U15.2@76.483,25.762 76.483,25.608 76.5,25.591 v1(76.5,24.25) ; v1(77.025,12.55) TR6.2@77.025,13.35 v1(77.975,13.35) ; L7.2@77.975,7.95 v2(79.1,7.95) ; C123.1@78.775,10.8 v2(79.675,10.8) ; C116.1@78.775,19.025 v2(78.775,19.925)
  Top w0.4: R132.1@68.225,7.725 C158.1@69.225,7.725 ; L9.1@68.933,13.053 v2(70.1,13.05) ; v2(70.825,20.075) L10.2@71.925,20.08
  L2C w0.2: v2(32.325,26.725) v2(33.475,26.725)
  L5C w0.2: v3(67.25,-1.825) v3(68.25,-1.825)
  Bottom w0.2: C44.1@43.414,14.317 43.414,15.069 44.03,15.685 v4(44.555,15.685) ; v1(45.413,5.939) 45.438,5.964 C71.1@46.149,5.964 ; v9@51.775,-4.025 C162.1@52.664,-4.025 ; v2(51.775,-3) 51.784,-3.009 C163.1@52.664,-3.009 ; v2(51.775,-2.025) 51.778,-2.028 C164.1@52.664,-2.028 52.664,-1.139 v2(52.65,-1.125) ; R138.1@53.617,1.82 v1(53.617,2.535) ; C18.2@54.807,34.38 54.807,35.297 v4(54.811,35.301) ; v2(54.925,-4) C156.1@55.812,-4 ; C185.1@55,6.875 v2(56,6.875) ; v2(55,8.875) C186.1@55,7.875 v2(56,7.875) ; C184.1@55.65,5.675 v2(56.75,5.675) ; C187.1@56.139,4.472 v2@56.972,4.472 ; C189.1@57.862,4.349 v2@57.862,5.288 ; v2(58.875,5.3) 58.887,5.288 C188.1@58.887,4.349 ; v3(58.9,-5.75) C170.1@59.9,-5.75 ; v4(59.35,-4.875) C153.1@59.35,-4 ; v2@59.803,4.297 C183.1@60.714,4.297 ; v2(60.475,-4.1) C168.1@60.475,-3.2 ; v2(60.7,5.3) 60.714,5.286 C183.1@60.714,4.297 ; v2@61.475,4.297 C183.1@60.714,4.297 ; v2(64,6.925) D10.3@65.1,6.925 ; C137.1@64.098,16.186 v2@65.086,16.186 ; v1(64.9,4.625) C191.2@65.8,4.625 v1(65.8,3.775) ; v3(67.25,-1.825) C181.1@67.25,-0.825 ; C190.2@68.075,8.675 v1(68.075,9.45) ; C169.1@68.25,-4.325 v4(68.25,-3.525) ; v3(68.25,-1.825) C182.1@68.25,-0.825 ; v4(69.7,-3.8) C161.1@69.7,-5.075 v2(71.1,-5.075) ; C176.1@70.325,6.6 v2(70.325,7.575) ; v2(70.575,0.175) C179.1@71.525,0.175 ; C148.1@71.651,26.69 v1(71.651,27.325) ; C177.1@72.325,7.575 v2(72.325,8.65) ; C178.1@73.325,7.575 v2(73.325,8.65) ; v1@74.832,24.246 C96.2@75.528,24.246 v1@76.496,24.246 ; v3@75.008,30.508 R81.2@75.918,30.508 ; v2@75.008,31.458 C93.2@75.918,31.458 ; C95.2@75.525,26.733 v1(75.525,27.75) ; v1(76.3,28.265) C91.2@77.292,28.265 ; v1@76.501,24.251 R83.2@76.501,25.483
  Bottom w0.3: v4(56.489,0.047) 56.639,0.197 U2.2@57.389,0.197 ; U2.4@57.389,1.197 U2.4@57.389,1.297
  Bottom w0.4: v4(61.475,2.45) 61.975,2.45 ; C180.1@61.964,1.647 61.975,1.658 61.975,2.45 ; v4(62.475,2.45) 61.975,2.45 ; C165.1@67.025,-4.325 C169.1@68.25,-4.325
  Bottom w0.5: v4(56.839,1.697) 57.339,1.697 57.389,1.647 U2.4@57.389,1.297
  other v1: 20.421,-4.168 22.58,-4.092 13.612,-1.656 14.247,-0.767 1.928,-0.513 58.9,-0.05 36.599,0.224 58.375,0.45 59.4,0.45 2.944,0.63 37.513,0.681 58.875,0.95 1.293,1.773 52.728,2.154 2.944,3.297 34.44,3.297 9.802,3.932 11.707,3.932 43.863,3.957 33.932,4.059 10.818,4.821 64.9,5.4 2.69,7.361 3.325,7.361 6.627,7.361 38.123,7.361 41.933,7.361 64.525,7.75 2.69,8.631 3.325,8.631 6.627,8.631 48.41,10.155 81.175,13.5 48.41,14.219 70.635,22.093 74.826,24.252 72.311,26.665 70.889,26.69 64.3,34.925 55.827,35.123 61.618,38.349 61.618,39.111 69.111,40.127
  other v2: 41.025,-9.375 3.825,-9.3 16.2,-9.3 44.8,-9.275 48.675,-9.075 36.45,-9 10.3,-8.95 73.525,-8.85 52.475,-8.825 66.475,-8.825 71.575,-7 40,-5.225 77.4,-5.15 47.675,-4.975 43.125,-4.95 35.075,-4.875 -1.5,-4.85 31.1,-4.725 49.15,-4.3 16.5,-3.375 37.125,-3.375 50.475,-2.875 23.375,-1.8 -1.5,-1.675 46.1,-1.675 47.5,-1.35 24.425,-0.6 18.8,-0.475 34.5,-0.45 21.8,-0.35 48.875,-0.025 32.475,0.3 42.825,0.775 31.725,2.35 -1.5,2.525 70.525,2.85 59.8,4.3 61.491,4.313 56.975,4.475 57.85,5.3 75.85,5.425 51.2,5.475 8.775,6.525 58.575,7.05 33.7,7.1 28.4,7.15 -1.5,7.425 80.775,7.5 52.75,8.4 57.275,8.525 63.55,8.575 -1.5,8.7 61.825,9.25 63.425,12.3 58.45,12.7 72.475,13.075 61.725,13.775 60.125,15.5 53.725,15.95 51.6,16.025 65.1,16.2 58.125,17.325 31.6,18.05 69.825,19.7 36.35,20.95 53.875,21.775 57.297,22.35 52.325,22.4 37.425,22.7 44.05,22.875 79.675,24.125 54.175,27.05 57.475,27.05 31.125,27.15 32.625,28.525 71.3,28.525 75,31.45 58.575,31.825 72.475,32.675 80.925,33 81.15,37.225 55.15,38.575 76.45,42.025 55.3,42.2 61.65,42.2 72.625,42.2 65.1,42.225
  other v3: 50.475,-4.825 75.475,-4.825 56.3,-1.875 40.075,-1.775 50.475,1.975 75.475,1.975 50.475,8.875 75.475,8.875 64.725,10.025 52.475,10.675 59.475,10.675 66.5,10.675 73.475,10.675 50.95,12.975 31.45,14.3 69.25,15.625 48.025,18.825 62.65,20.35 40.075,22.35 61.725,26.325 74.125,29.425 75,30.5 70.35,32.775 76.05,34.15 59.05,34.4 61.55,36.325 64.675,36.65 59.775,36.75
  other v4: 48.525,15.175 48.525,16.4 51.45,19.15 48.55,20.425 47.965,21.056 40.475,26.7
  other v5: 61.2,-6.15 61.525,-0.925 63.95,-0.65 54.375,-0.15 49.875,1.3 55,1.375 51.35,2.2 69.25,9.975 65.675,11.85 57.15,19.15 53.7,19.25 43.4,19.65 44.425,19.65 45.45,19.65 71.725,24.175 53.725,24.575 57.2,24.65 81.075,26.55 66.075,28.35 58.975,28.425 64.275,28.65 60.8,28.75 55.05,29 56.55,30.525 78.075,31.675 62.35,31.725 64.525,31.775 60.6,31.825 73.85,31.9
  other v6: 38,9.05 40,9.05 42,9.05 39,10.05 41,10.05 38,11.05 40,11.05 42,11.05 39,12.05 41,12.05 38,13.05 40,13.05 42,13.05 39.517,30.778 41.517,30.778 43.517,30.778 40.517,31.778 42.517,31.778 39.517,32.778 41.517,32.778 43.517,32.778 40.517,33.778 42.517,33.778 39.517,34.778 41.517,34.778 43.517,34.778 67.822,35.635 68.922,35.635 68.922,36.735
  other v7: 65,21.538 65.9,21.538 66.8,21.538 67.7,21.538 68.6,21.538 65,22.438 68.6,22.438 65,23.338 68.6,23.338 65,24.238 68.6,24.238 65,25.138 65.9,25.138 66.8,25.138 67.7,25.138 68.6,25.138 66.722,34.535 67.822,34.535 68.922,34.535 70.022,34.535 66.722,35.635 70.022,35.635 66.722,36.735 70.022,36.735 66.722,37.835 67.822,37.835 68.922,37.835 70.022,37.835
  other v8: 37,8.05 39,8.05 41,8.05 43,8.05 37,10.05 43,10.05 37,12.05 43,12.05 37,14.05 39,14.05 41,14.05 43,14.05 38.517,29.778 40.517,29.778 42.517,29.778 44.517,29.778 38.517,31.778 44.517,31.778 38.517,33.778 44.517,33.778 38.517,35.778 40.517,35.778 42.517,35.778 44.517,35.778
  other v9: 51.775,-4.025
  other v10: 65.9,22.438 66.8,22.438 67.7,22.438 65.9,23.338 66.8,23.338 67.7,23.338 65.9,24.238 66.8,24.238 67.7,24.238
  other v12: 58.389,-0.053 59.389,-0.053 58.889,0.447 58.389,0.947 59.389,0.947
  other v14: 54.709,13.432 55.751,13.432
